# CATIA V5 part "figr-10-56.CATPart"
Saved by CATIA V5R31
Part number: Part1
Bounding box of the stored display mesh (mm): x -101.896 to 127.212, y -67.72 to 67.298, z 0 to 0
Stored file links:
  D:\PROJECTS\Project 2021\US EDITION\CATIA V5 6R 2021\Resources\Part Files\c10_catia_v5_6r2021_prt\c10_catia_v5_6r2021_prt\figr-10-56.CATPart
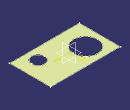
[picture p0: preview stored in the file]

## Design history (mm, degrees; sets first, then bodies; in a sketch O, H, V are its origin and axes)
Body1 (main body)
  Sketch1 on xy-plane, origin (0, 0, 0), H (1, 0, 0), V (0, 1, 0)
    line L1 (-101.8963, 67.298) -> (127.2122, 67.298)
    line L2 (127.2122, 67.298) -> (127.2122, -67.7199)
    line L3 (127.2122, -67.7199) -> (-101.8963, -67.7199)
    line L4 (-101.8963, -67.7199) -> (-101.8963, 67.298)
    horizontal: L1 H, L3 H
    vertical: L2 V, L4 V
  Sketch2 on xy-plane, origin (0, 0, 0), H (1, 0, 0), V (0, 1, 0)
    circle A1 centre (-45.2964, 9.2296) radius 39.3004
    circle A2 centre (71.0804, -29.9585) radius 20.9926
  Fill1: Boundary Sketch1, InnerBoundaries {fillinnerboundary Boundaries Sketch2}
